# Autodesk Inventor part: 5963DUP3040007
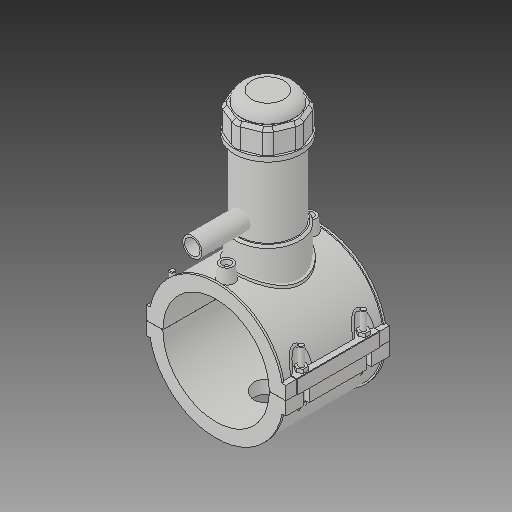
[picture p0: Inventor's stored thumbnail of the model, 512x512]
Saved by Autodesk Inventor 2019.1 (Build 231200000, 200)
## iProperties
Created: 2017-07
Part Number: 5963DUP3040007
Material: Generic
Description: PLASSON TAPPING SADDLE 4''DIPS x 3/4''CTS
Document SubType Name: Modeling
Designer: KIM
Density: 1 g/cm^3
Appearance: Default
Author: KIM
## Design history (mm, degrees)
derived "5963DBP_5963BUP.ipt"
feature "Solid1::5963DBP_5963BUP.ipt"
feature "Solid2::5963DBP_5963BUP.ipt"
feature "Solid3::5963DBP_5963BUP.ipt"
tag "TaggingFeature1"
body "Solid1"
body "Solid2"
body "Solid3"
other parameters: "d0" = 121.3, "d2" = 159.004, "d3" = 30.325, "d4" = 118.11, "d5" = 0, "d6" = 0.1, "d8" = 0, "d19" = 6, "d20" = 6, "d21" = 70.866, "d23" = 0, "d24" = 35.433, "d26" = 0, "d27" = 3, "d28" = 3, "d29" = 3, "d30" = 40.43333, "d31" = 6, "d32" = 0, "d33" = 0, "d34" = 0.6, "d40" = 78.21424, "d41" = 76.419, "d43" = 0, "d45" = 0, "d47" = 146.072, "d70" = 15, "d72" = 0, "d73" = 6, "d75" = 5, "d76" = 0, "d77" = 6.065, "d78" = 90.65, "d79" = 15, "d80" = 47.244, "d82" = 5 deg, "d84" = 4, "d85" = 14, "d86" = 0, "d87" = 3, "d88" = 0, "d89" = 1, "d90" = 1, "d91" = 94.488, "d92" = 0, "d93" = 0.5, "d94" = 63.84211, "d96" = 153.42024, "d97" = 2.3622, "d98" = 0, "d120" = 140 deg, "d121" = 24.228, "d122" = 20 deg, "d123" = 300.824, "d124" = 90.2472, "d126" = 0, "d143" = 124.939, "d145" = 22.39385, "d149" = 1.8195, "d150" = 24.63323, "d153" = 118.11, "d154" = 0, "d156" = 75.206, "d157" = 160 deg, "d159" = 5.8224, "d161" = 1.8195, "d162" = 70.866, "d163" = 0, "d164" = 60.65, "d167" = 12.13, "d168" = 73.37171, "d170" = 3.4335, "d172" = 0, "d173" = 1, "d175" = 60.65, "d176" = 20 deg, "d177" = 8.491, "d178" = 29.112, "d180" = 0, "d183" = 11.6448, "d184" = 6.7928, "d185" = 38.38575, "d186" = 38.38575, "d187" = 75.206, "d188" = 8.7336, "d189" = 8.491, "d190" = 0, "d191" = 112.809, "d193" = 7.3248, "d194" = 4.13385, "d195" = 90 deg, "d197" = 0, "d199" = 0, "d200" = 14.556, "d202" = 0, "d203" = 177.038, "d204" = 72.59805, "d205" = 53.4933, "d206" = 64.95615, "d207" = 132.7785, "d208" = 138.08964, "d209" = 164.64534, "d210" = 65.72034, "d211" = 76.419, "d212" = 61.1352, "d213" = 48.5766, "d216" = 0, "d217" = 12.13, "d218" = 12.13, "d219" = 2.426, "d222" = 121.3, "d224" = 0, "d225" = 65.024, "d226" = 22.1, "d227" = 17.68, "d228" = 86.106, "d230" = 3.639, "d_" = 121.3, "B_" = 159.004, "L_" = 118.11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
